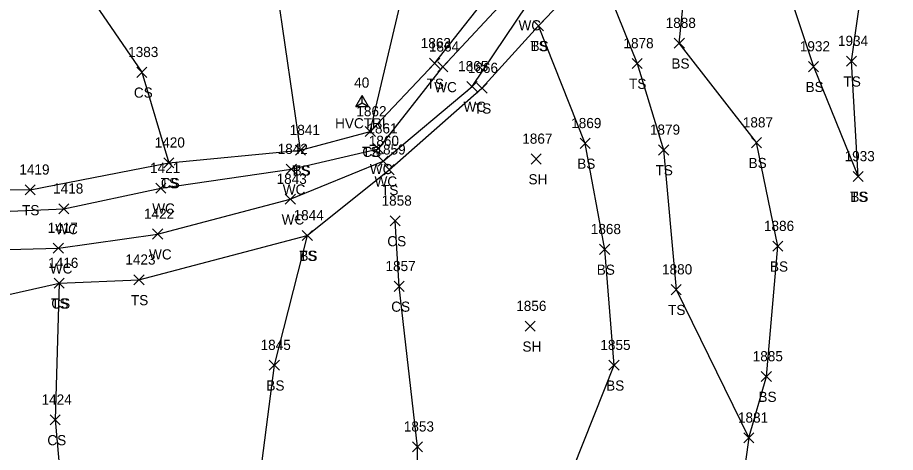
# Model space of a CAD drawing. Extents: x 1551995 to 1555700, y 777276 to 783130.
# Drawn here: x 1554974.4 to 1555147.4, y 777620.1 to 777705.7 of the extents above; entities that cross this region are included whole.
import ezdxf

# ---------------------------------------------------------------- set-up
doc = ezdxf.new("R2010")
doc.units = 0
for name, color, linetype in [('C_A', 7, 'Continuous'), ('C_I', 7, 'Continuous'), ('CPSM', 7, 'Continuous'), ('L_A', 7, 'Continuous'), ('L_I', 7, 'Continuous'), ('L_TIC', 7, 'Continuous'), ('LAWE', 7, 'Continuous'), ('LELB', 7, 'Continuous')]:
    doc.layers.add(name, color=color, linetype=linetype)

msp = doc.modelspace()

# ---------------------------------------------------------------- linework, layer by layer
at = {"layer": 'CPSM'}
for p, q in [((1555041.01, 777688.2), (1555042.26, 777690.37)), ((1555043.51, 777688.2), (1555042.26, 777690.37)), ((1555042.26, 777688.92), (1555042.26, 777690.37)), ((1555041.01, 777688.2), (1555042.26, 777688.92)), ((1555041.01, 777688.2), (1555043.51, 777688.2)), ((1555042.26, 777688.92), (1555042.26, 777688.92)), ((1555042.26, 777688.92), (1555043.51, 777688.2))]:
    msp.add_line(p, q, dxfattribs=at)
at = {"layer": 'L_TIC'}
for points in [[(1555076.02, 777703.11), (1555078.02, 777705.11)], [(1555078.02, 777703.11), (1555076.02, 777705.11)], [(1555076.02, 777703.11), (1555078.02, 777705.11)], [(1555078.02, 777703.11), (1555076.02, 777705.11)], [(1555103.78, 777699.68), (1555105.78, 777701.68)], [(1555105.78, 777699.68), (1555103.78, 777701.68)], [(1555137.72, 777696.14), (1555139.72, 777698.14)], [(1555139.72, 777696.14), (1555137.72, 777698.14)], [(1555055.56, 777695.7), (1555057.56, 777697.7)], [(1555057.56, 777695.7), (1555055.56, 777697.7)], [(1555057.18, 777695.03), (1555059.18, 777697.03)], [(1555059.18, 777695.03), (1555057.18, 777697.03)], [(1555095.46, 777695.69), (1555097.46, 777697.69)], [(1555097.46, 777695.69), (1555095.46, 777697.69)], [(1555130.21, 777695.07), (1555132.21, 777697.07)], [(1555132.21, 777695.07), (1555130.21, 777697.07)], [(1554997.86, 777693.95), (1554999.86, 777695.95)], [(1554999.86, 777693.95), (1554997.86, 777695.95)], [(1555062.93, 777691.17), (1555064.93, 777693.17)], [(1555064.93, 777691.17), (1555062.93, 777693.17)], [(1555064.89, 777690.82), (1555066.89, 777692.82)], [(1555066.89, 777690.82), (1555064.89, 777692.82)], [(1555042.88, 777682.29), (1555044.88, 777684.29)], [(1555044.88, 777682.29), (1555042.88, 777684.29)], [(1555042.88, 777682.29), (1555044.88, 777684.29)], [(1555044.88, 777682.29), (1555042.88, 777684.29)], [(1555044.48, 777678.91), (1555046.48, 777680.91)], [(1555046.48, 777678.91), (1555044.48, 777680.91)], [(1555085.22, 777679.96), (1555087.22, 777681.96)], [(1555087.22, 777679.96), (1555085.22, 777681.96)], [(1555118.98, 777680.1), (1555120.98, 777682.1)], [(1555120.98, 777680.1), (1555118.98, 777682.1)], [(1555029.13, 777678.61), (1555031.13, 777680.61)], [(1555031.13, 777678.61), (1555029.13, 777680.61)], [(1555029.13, 777678.61), (1555031.13, 777680.61)], [(1555031.13, 777678.61), (1555029.13, 777680.61)], [(1555100.68, 777678.67), (1555102.68, 777680.67)], [(1555102.68, 777678.67), (1555100.68, 777680.67)], [(1555003.18, 777676.14), (1555005.18, 777678.14)], [(1555005.18, 777676.14), (1555003.18, 777678.14)], [(1555003.18, 777676.14), (1555005.18, 777678.14)], [(1555005.18, 777676.14), (1555003.18, 777678.14)], [(1555045.42, 777676.46), (1555047.42, 777678.46)], [(1555047.42, 777676.46), (1555045.42, 777678.46)], [(1555075.57, 777676.89), (1555077.57, 777678.89)], [(1555077.57, 777676.89), (1555075.57, 777678.89)], [(1555027.32, 777674.88), (1555029.32, 777676.88)], [(1555029.32, 777674.88), (1555027.32, 777676.88)], [(1555046.6, 777674.77), (1555048.6, 777676.77)], [(1555048.6, 777674.77), (1555046.6, 777676.77)], [(1555139.03, 777673.45), (1555141.03, 777675.45)], [(1555141.03, 777673.45), (1555139.03, 777675.45)], [(1555139.03, 777673.45), (1555141.03, 777675.45)], [(1555141.03, 777673.45), (1555139.03, 777675.45)], [(1554975.86, 777670.82), (1554977.86, 777672.82)], [(1554977.86, 777670.82), (1554975.86, 777672.82)], [(1555001.61, 777671.14), (1555003.61, 777673.14)], [(1555003.61, 777671.14), (1555001.61, 777673.14)], [(1555027.12, 777668.98), (1555029.12, 777670.98)], [(1555029.12, 777668.98), (1555027.12, 777670.98)], [(1554982.51, 777667.08), (1554984.51, 777669.08)], [(1554984.51, 777667.08), (1554982.51, 777669.08)], [(1555047.8, 777664.7), (1555049.8, 777666.7)], [(1555049.8, 777664.7), (1555047.8, 777666.7)], [(1555000.98, 777662.11), (1555002.98, 777664.11)], [(1555002.98, 777662.11), (1555000.98, 777664.11)], [(1555030.47, 777661.83), (1555032.47, 777663.83)], [(1555032.47, 777661.83), (1555030.47, 777663.83)], [(1555030.47, 777661.83), (1555032.47, 777663.83)], [(1555032.47, 777661.83), (1555030.47, 777663.83)], [(1555123.19, 777659.72), (1555125.19, 777661.72)], [(1555125.19, 777659.72), (1555123.19, 777661.72)], [(1554981.43, 777659.34), (1554983.43, 777661.34)], [(1554983.43, 777659.34), (1554981.43, 777661.34)], [(1555089.07, 777659.1), (1555091.07, 777661.1)], [(1555091.07, 777659.1), (1555089.07, 777661.1)], [(1554997.31, 777653.1), (1554999.31, 777655.1)], [(1554999.31, 777653.1), (1554997.31, 777655.1)], [(1554981.59, 777652.45), (1554983.59, 777654.45)], [(1554983.59, 777652.45), (1554981.59, 777654.45)], [(1554981.59, 777652.45), (1554983.59, 777654.45)], [(1554983.59, 777652.45), (1554981.59, 777654.45)], [(1555048.57, 777651.82), (1555050.57, 777653.82)], [(1555050.57, 777651.82), (1555048.57, 777653.82)], [(1555103.15, 777651.17), (1555105.15, 777653.17)], [(1555105.15, 777651.17), (1555103.15, 777653.17)], [(1555074.39, 777643.97), (1555076.39, 777645.97)], [(1555076.39, 777643.97), (1555074.39, 777645.97)], [(1555023.97, 777636.3), (1555025.97, 777638.3)], [(1555025.97, 777636.3), (1555023.97, 777638.3)], [(1555090.91, 777636.29), (1555092.91, 777638.29)], [(1555092.91, 777636.29), (1555090.91, 777638.29)], [(1555120.93, 777634.07), (1555122.93, 777636.07)], [(1555122.93, 777634.07), (1555120.93, 777636.07)], [(1554980.81, 777625.54), (1554982.81, 777627.54)], [(1554982.81, 777625.54), (1554980.81, 777627.54)], [(1555117.46, 777621.99), (1555119.46, 777623.99)], [(1555119.46, 777621.99), (1555117.46, 777623.99)], [(1555117.46, 777621.99), (1555119.46, 777623.99)], [(1555119.46, 777621.99), (1555117.46, 777623.99)], [(1555052.18, 777620.24), (1555054.18, 777622.24)], [(1555054.18, 777620.24), (1555052.18, 777622.24)]]:
    msp.add_lwpolyline(points, dxfattribs=at)
at = {"layer": 'LAWE'}
for points in [[(1554896.13, 777669.49), (1554914.18, 777672.74), (1554933.67, 777664.23), (1554957.57, 777659.67), (1554982.43, 777660.34), (1555001.98, 777663.11), (1555028.12, 777669.98), (1555046.42, 777677.46), (1555063.93, 777692.17), (1555074.78, 777708.2), (1555088.15, 777717.7), (1555098.22, 777729.19), (1555108.92, 777737.75), (1555125.5, 777739.97), (1555133.42, 777752.91), (1555147.36, 777756.73)], [(1554957.7, 777666.95), (1554983.51, 777668.08), (1555002.61, 777672.14), (1555028.32, 777675.88), (1555045.48, 777679.91), (1555058.18, 777696.03), (1555071.93, 777710.76)]]:
    msp.add_lwpolyline(points, dxfattribs=at)
at = {"layer": 'LELB'}
for points in [[(1555140.03, 777674.45), (1555138.72, 777697.14), (1555141.32, 777715.72), (1555143.67, 777730.91), (1555146.42, 777748.49)], [(1554938.36, 777737.56), (1554957.8, 777735.77), (1554982.18, 777719.34), (1554998.86, 777694.95), (1555004.18, 777677.14)], [(1555031.47, 777662.83), (1555047.6, 777675.77), (1555065.89, 777691.82), (1555077.02, 777704.11), (1555088.61, 777716.24), (1555100.93, 777725.39), (1555108.92, 777735.98), (1555125.47, 777736.42)], [(1555125.47, 777736.42), (1555129.52, 777728.47), (1555125.79, 777712.48), (1555131.21, 777696.07), (1555140.03, 777674.45)], [(1555030.13, 777679.61), (1555024.1, 777721.15), (1555030.87, 777735.22)], [(1555043.88, 777683.29), (1555053.64, 777724.75)], [(1555118.46, 777622.99), (1555121.93, 777635.07), (1555124.19, 777660.72), (1555119.98, 777681.1), (1555104.78, 777700.68), (1555105.85, 777711.42), (1555100.93, 777725.39)], [(1555088.61, 777716.24), (1555096.46, 777696.69), (1555101.68, 777679.67), (1555104.15, 777652.17), (1555118.46, 777622.99), (1555114.53, 777595.03), (1555107.52, 777571.18), (1555085.84, 777534.97)], [(1554960.8, 777672.01), (1554976.86, 777671.82), (1555004.18, 777677.14), (1555030.13, 777679.61), (1555043.88, 777683.29), (1555056.56, 777696.7), (1555070.58, 777714.5)], [(1555067.41, 777564.16), (1555074.15, 777586.87), (1555081.9, 777612.07), (1555091.91, 777637.29), (1555090.07, 777660.1), (1555086.22, 777680.96), (1555077.02, 777704.11)], [(1554873.83, 777672.65), (1554885.1, 777668.28), (1554896.47, 777665.61), (1554911.4, 777664.89), (1554930.69, 777655.48), (1554958.85, 777648.16), (1554982.59, 777653.45), (1554998.31, 777654.1)], [(1555037.7, 777563.66), (1555053.13, 777597.92), (1555053.18, 777621.24), (1555049.57, 777652.82), (1555048.8, 777665.7)], [(1554998.31, 777654.1), (1555031.47, 777662.83)], [(1555031.47, 777662.83), (1555024.97, 777637.3), (1555021.46, 777610.34), (1555015.91, 777589.32), (1555014.3, 777566.28)], [(1554982.59, 777653.45), (1554981.81, 777626.54), (1554985.65, 777583.22), (1554991.78, 777538.05), (1554981.16, 777471.14)]]:
    msp.add_lwpolyline(points, dxfattribs=at)

# ---------------------------------------------------------------- texts
at = {"layer": 'C_A'}
msp.add_text('HVCTRL', height=2, dxfattribs=at).set_placement((1555036.95, 777683.92))
at = {"layer": 'C_I'}
msp.add_text('40', height=2, dxfattribs=at).set_placement((1555040.71, 777691.92))
at = {"layer": 'L_A'}
for s, p in [('WC', (1555073.09, 777703.2)), ('TS', (1555075.43, 777699.11)), ('BS', (1555075.46, 777699.11)), ('BS', (1555103.22, 777695.68)), ('TS', (1555054.97, 777691.7)), ('WC', (1555056.49, 777691.03)), ('TS', (1555094.87, 777691.69)), ('BS', (1555129.65, 777691.07)), ('TS', (1555137.13, 777692.14)), ('CS', (1554997.3, 777689.95)), ('WC', (1555062.24, 777687.17)), ('TS', (1555064.3, 777686.82)), ('TS', (1555042.29, 777678.29)), ('CS', (1555042.32, 777678.29)), ('BS', (1555084.66, 777675.96)), ('BS', (1555118.42, 777676.1)), ('TS', (1555028.54, 777674.61)), ('BS', (1555028.57, 777674.61)), ('WC', (1555043.79, 777674.91)), ('TS', (1555100.09, 777674.67)), ('TS', (1555002.59, 777672.14)), ('CS', (1555002.62, 777672.14)), ('WC', (1555044.72, 777672.46)), ('SH', (1555075.06, 777672.89)), ('WC', (1555026.63, 777670.88)), ('TS', (1555046.01, 777670.77)), ('TS', (1555138.44, 777669.45)), ('BS', (1555138.47, 777669.45)), ('TS', (1554975.27, 777666.82)), ('WC', (1555000.92, 777667.14)), ('WC', (1555026.42, 777664.98)), ('WC', (1554981.82, 777663.08)), ('CS', (1555047.24, 777660.7)), ('WC', (1555000.29, 777658.11)), ('TS', (1555029.88, 777657.83)), ('BS', (1555029.91, 777657.83)), ('WC', (1554980.74, 777655.34)), ('BS', (1555088.51, 777655.1)), ('BS', (1555122.64, 777655.72)), ('TS', (1554981, 777648.45)), ('CS', (1554981.03, 777648.45)), ('TS', (1554996.72, 777649.1)), ('CS', (1555048.01, 777647.82)), ('TS', (1555102.56, 777647.17)), ('SH', (1555073.87, 777639.97)), ('BS', (1555023.41, 777632.3)), ('BS', (1555090.36, 777632.29)), ('BS', (1555120.37, 777630.07)), ('CS', (1554980.25, 777621.54))]:
    msp.add_text(s, height=2, dxfattribs=at).set_placement(p)
at = {"layer": 'L_I'}
for s, p in [('1888', (1555102.09, 777703.68)), ('1863', (1555053.82, 777699.7)), ('1878', (1555093.77, 777699.69)), ('1934', (1555136.03, 777700.14)), ('1383', (1554996.17, 777697.95)), ('1864', (1555055.44, 777699.03)), ('1932', (1555128.52, 777699.07)), ('1865', (1555061.19, 777695.17)), ('1866', (1555063.1, 777694.82)), ('1862', (1555041.14, 777686.29)), ('1862', (1555041.14, 777686.29)), ('1869', (1555083.47, 777683.96)), ('1887', (1555117.29, 777684.1)), ('1841', (1555028.01, 777682.61)), ('1841', (1555028.01, 777682.61)), ('1861', (1555043.31, 777682.91)), ('1879', (1555098.98, 777682.67)), ('1860', (1555043.59, 777680.46)), ('1867', (1555073.83, 777680.89)), ('1420', (1555001.4, 777680.14)), ('1420', (1555001.4, 777680.14)), ('1842', (1555025.63, 777678.88)), ('1859', (1555044.9, 777678.77)), ('1933', (1555137.34, 777677.45)), ('1933', (1555137.34, 777677.45)), ('1419', (1554974.73, 777674.82)), ('1421', (1555000.49, 777675.14)), ('1843', (1555025.42, 777672.98)), ('1418', (1554981.39, 777671.08)), ('1858', (1555046.11, 777668.7)), ('1422', (1554999.29, 777666.11)), ('1844', (1555028.77, 777665.83)), ('1844', (1555028.77, 777665.83)), ('1417', (1554980.31, 777663.34)), ('1886', (1555121.45, 777663.72)), ('1868', (1555087.33, 777663.1)), ('1416', (1554980.41, 777656.45)), ('1416', (1554980.41, 777656.45)), ('1423', (1554995.62, 777657.1)), ('1857', (1555046.88, 777655.82)), ('1880', (1555101.37, 777655.17)), ('1856', (1555072.64, 777647.97)), ('1845', (1555022.27, 777640.3)), ('1855', (1555089.22, 777640.29)), ('1885', (1555119.24, 777638.07)), ('1424', (1554979.11, 777629.54)), ('1881', (1555116.33, 777625.99)), ('1881', (1555116.33, 777625.99)), ('1853', (1555050.49, 777624.24))]:
    msp.add_text(s, height=2, dxfattribs=at).set_placement(p)

doc.saveas('drawing.dxf')
